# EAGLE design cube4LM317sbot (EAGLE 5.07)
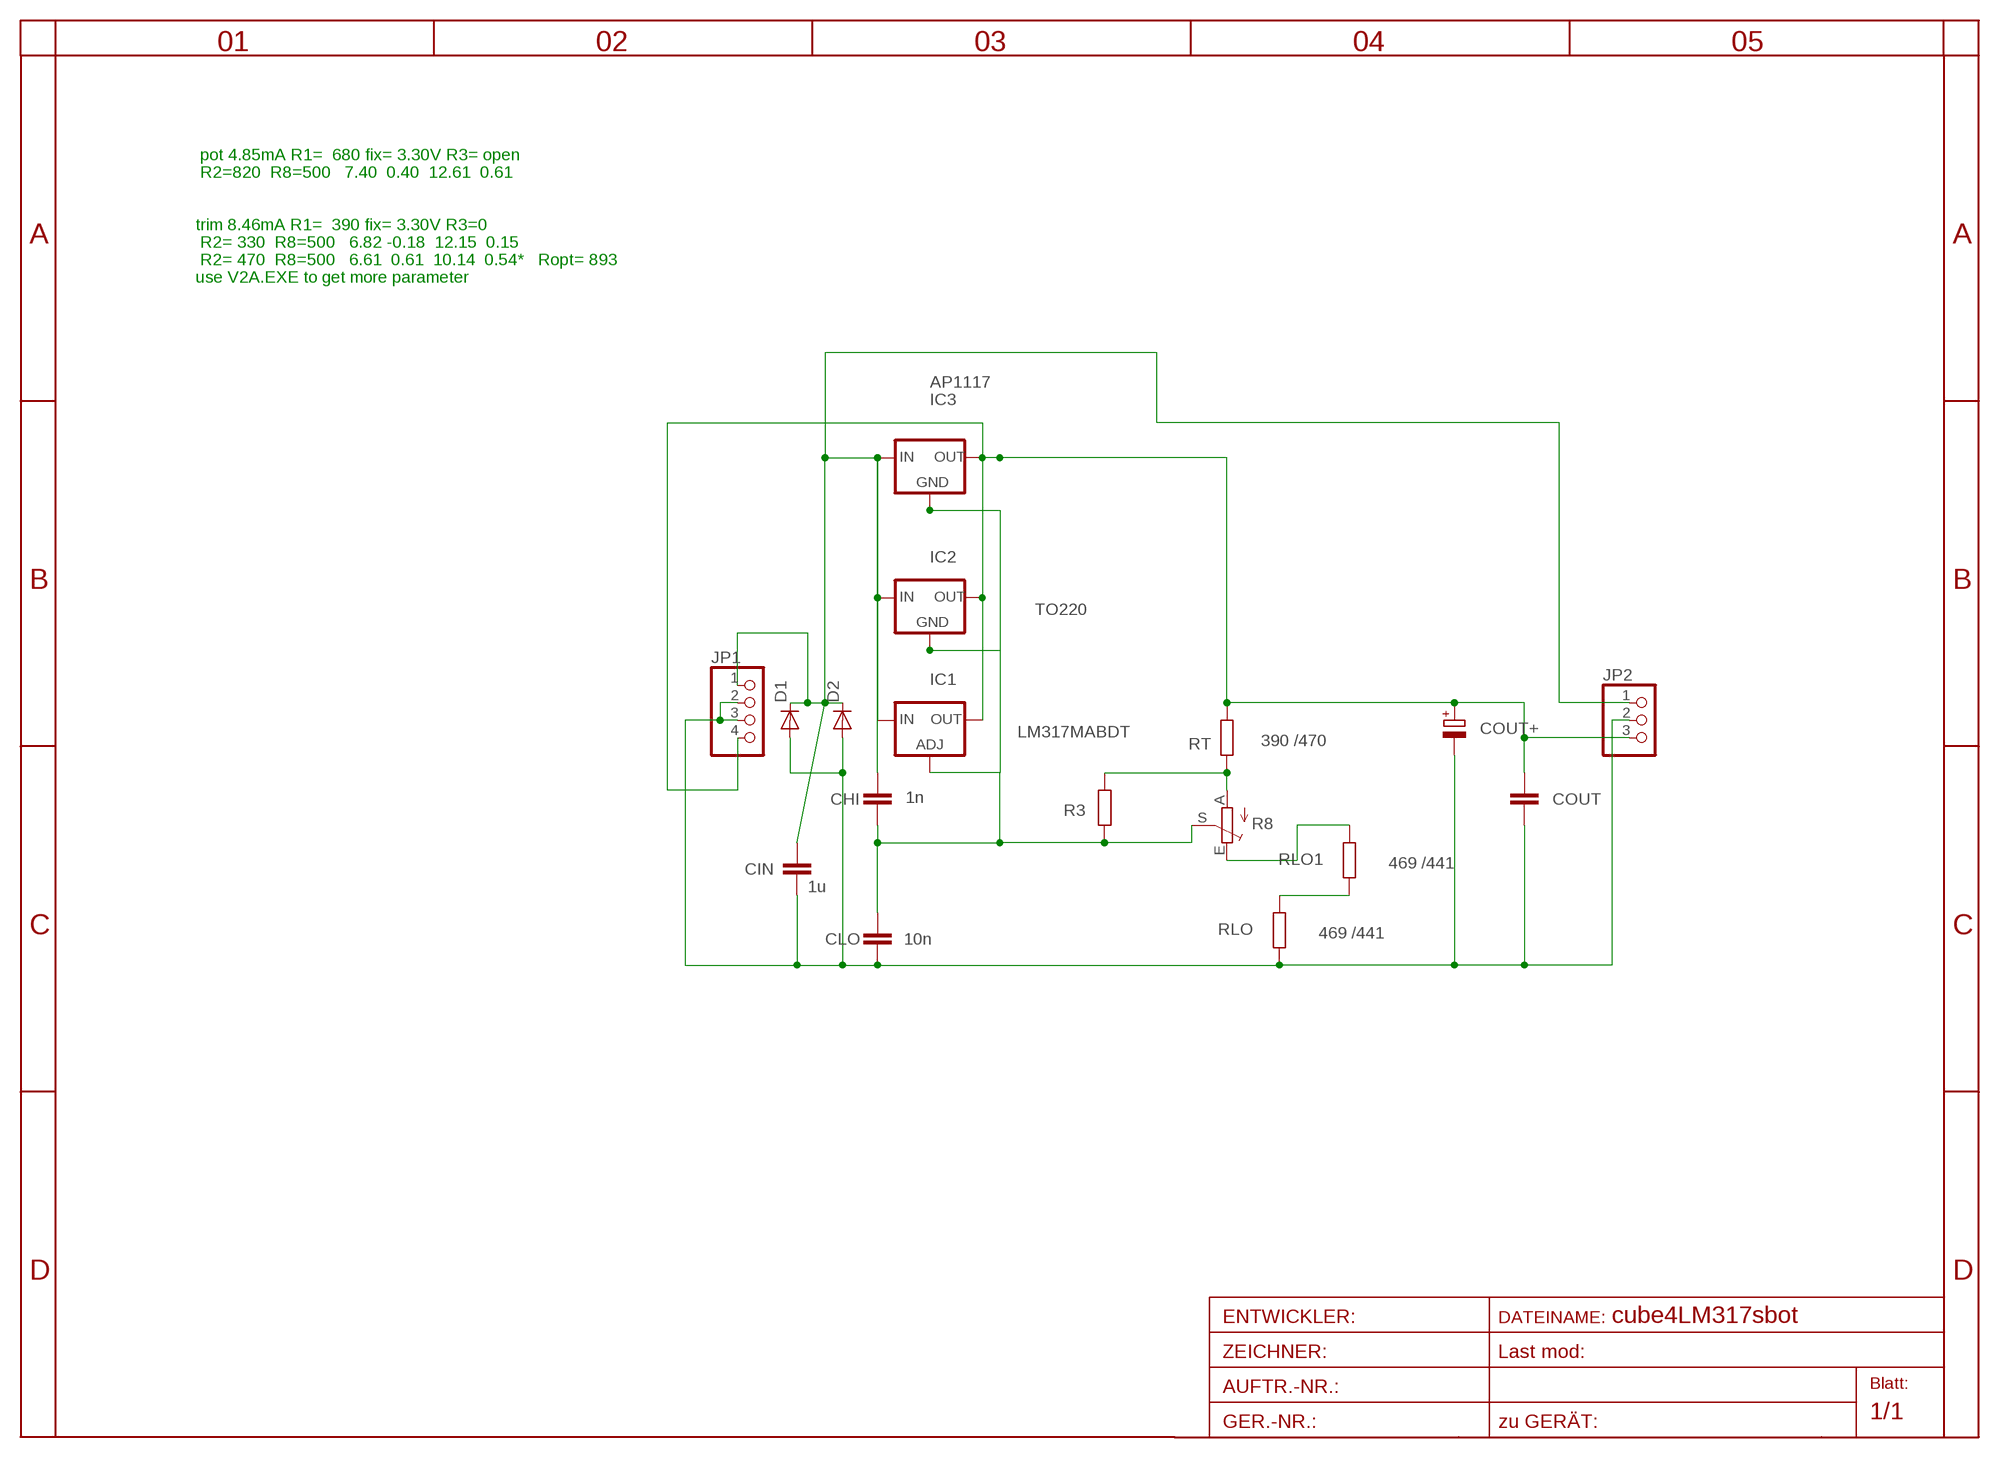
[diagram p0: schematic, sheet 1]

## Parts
CHI  1n  C-EUC0805  [C0805]
CIN  1u  C-EUC1206  [C1206]
CLO  10n  C-EUC0805  [C0805]
COUT  C-EUC1206  [C1206]
COUT+  CPOL-EUE2.5-6  [E2,5-6]
D1  DIODE-MINIMELF  [MINIMELF]
D2  DIODE-MINIMELF  [MINIMELF]
IC1  LM317MABDT  [DPACK]
IC2  TO220  78XXS  [78XXS]
IC3  AP1117  [SOT223]
JP1  PINHD-1X4  [1X04]
JP2  PINHD-1X3  [1X03]
R3  R-EU_R0805  [R0805]
R8  TRIM_EU-RAND160  [RANDL]
RLO  469 /441  R-EU_R0805  [R0805]
RLO1  469 /441  R-EU_R0805  [R0805]
RT  390 /470  R-EU_R0805  [R0805]

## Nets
GND: CIN.2 CLO.2 COUT+.- COUT.2 D1.A D2.A JP1.2 JP1.3 JP2.2 RLO.1
IN: CHI.1 CIN.1 D1.C D2.C IC1.3(IN) IC2.IN IC3.3(IN) JP1.1 JP2.1
N$1: R8.E RLO1.2
N$2: RLO1.1 RLO.2
N$4: CHI.2 CLO.1 IC1.1(ADJ) IC2.GND IC3.1(GND) R3.1 R8.S
N$7: R3.2 R8.A RT.1
OUT: COUT+.+ COUT.1 IC1.4(OUT) IC2.OUT IC3.2(OUT) IC3.4(TAB) JP1.4 JP2.3 RT.2

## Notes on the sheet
- pot 4.85mA R1=  680 fix= 3.30V R3= open
- R2=820  R8=500   7.40  0.40  12.61  0.61
- trim 8.46mA R1=  390 fix= 3.30V R3=0
- R2= 330  R8=500   6.82 -0.18  12.15  0.15
- R2= 470  R8=500   6.61  0.61  10.14  0.54*   Ropt= 893
- use V2A.EXE to get more parameter

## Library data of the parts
CHI CIN CLO COUT = rcl:C-EU: CAPACITOR, European symbol
COUT+ = rcl:CPOL-EU: POLARIZED CAPACITOR, European symbol
D1 D2 = diode-1:DIODE-: DIODE
IC1 = v-reg:LM317?*: 500 mA Adjustable Output Positive Voltage Regulator Source: http://www.onsemi.co.jp .. LM317M-D.PDF
IC2 = v-reg:78XXS: VOLTAGE REGULATOR
IC3 = v-reg:AP1117
JP1 = pinhead:PINHD-1X4: PIN HEADER
JP2 = pinhead:PINHD-1X3: PIN HEADER
R3 RLO RLO1 RT = rcl:R-EU_: RESISTOR, European symbol
R8 = pot:TRIM_EU-: POTENTIOMETER

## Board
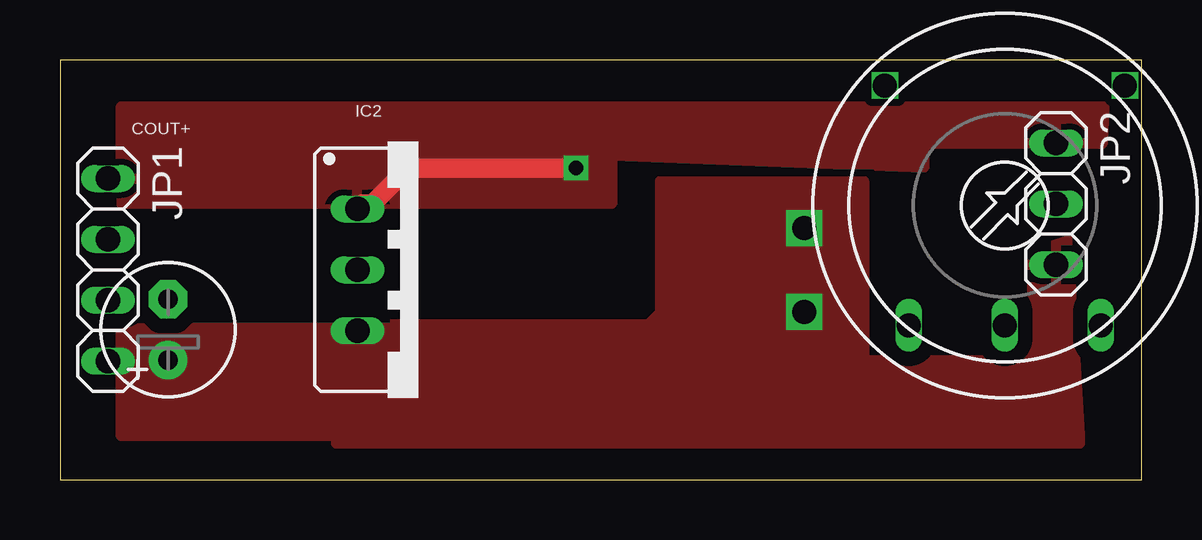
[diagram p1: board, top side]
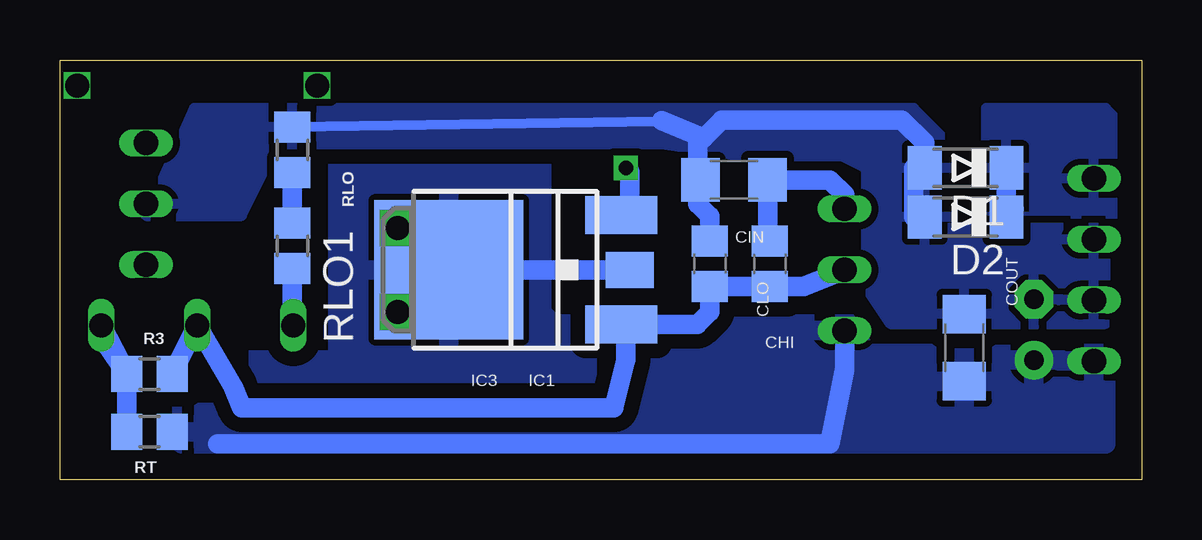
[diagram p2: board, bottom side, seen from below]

Size 45.08 x 17.5 mm. Coordinates in mm from the lower left corner, seen from the top.
Outline: 0,0 45.08,0 45.08,17.5 0,17.5 0,0
Copper layers (1*16): Top 0.035mm / dielectric 1.5mm / Bottom 0.035mm
Design rules "default": minimum track width 10mil, minimum drill 20mil, track to track 8mil, track to pad 8mil, pad to pad 8mil, via to via 8mil, smd to smd 8mil, copper to edge 40mil, drill to drill 8mil, minimum pad ring 1mil, minimum via ring 8mil, stop-mask expansion 4mil, vias tented up to drill 0mil, thermal gap 10mil

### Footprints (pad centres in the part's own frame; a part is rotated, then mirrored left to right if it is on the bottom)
C0805 = smd 1.3 x 1.5: 1 -0.95,0; 2 0.95,0
C1206 = smd 1.6 x 1.8: 1 -1.4,0; 2 1.4,0
E2,5-6 = drill 0.8 pad 1.6 round: + -1.27,0 | drill 0.8 pad 1.6 octagon: - 1.27,0
MINIMELF = smd 1.4 x 1.8: A 1.7,0; C -1.7,0
DPACK = smd 1.6 x 3: 1 -2.28,-4.8; 3 2.28,-4.8 | smd 5.8 x 6.2: 4 0,2.38
78XXS = drill 1.016 long: GND 0,-2.54; IN -2.54,-2.54; OUT 2.54,-2.54
SOT223 = smd 1.5 x 2: 1 -2.3,-3.15; 2 0,-3.15; 3 2.3,-3.15 | smd 3.8 x 2: 4 0,3.15
1X04 = drill 1.016 long: 1 -3.81,0; 2 -1.27,0; 3 1.27,0; 4 3.81,0
1X03 = drill 1.016 long: 1 -2.54,0; 2 0,0; 3 2.54,0
R0805 = smd 1.3 x 1.5: 1 -0.95,0; 2 0.95,0
RANDL = drill 1 long: A -4,5; E 4,5; S 0,5 | drill 1 square: P$1 -5,-5; P$2 5,-5

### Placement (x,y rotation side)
CHI  15.5,9 270 bottom
CIN  17,12.5 180 bottom
CLO  18,9 90 bottom
COUT  7.4,5.5 90 bottom
COUT+  4.5,6.25 90 top
D1  7.35,13 180 bottom
D2  7.35,10.95 180 bottom
IC1  26.5,8.75 90 bottom
IC2  14.93,8.75 270 top
IC3  24.5,8.75 90 bottom
JP1  2,8.75 270 top
JP2  41.5,11.5 270 top
R3  41.35,4.4 180 bottom
R8  39.37,11.43 180 top
RLO  35.4,13.75 270 bottom
RLO1  35.4,9.75 270 bottom
RT  41.35,2 0 bottom

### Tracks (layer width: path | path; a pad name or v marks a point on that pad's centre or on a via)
GND
  Bottom 0.406: RLO.1 20.06,14.92 20.01,14.97
  Bottom 0.813: CLO.2 18,11 18.5,11.5 18.5,12.6 | D2.A 9.5,10.95 9.5,13 D1.A 9.05,14.05 10,15 17.5,15 18.25,14.25 | 18.25,14.25 18.5,14 18.5,12.6 | 18.5,12.6 CIN.2 | 18.25,14.25 20.01,14.97
  pour Bottom (isolate 0.305): 1.5,10.5 8,10.5 8,14 9.5,15.5 39.5,15.5 41.5,11 37.5,11 36.5,13 36.5,14 20,14 17.1,13.55 16,13.5 12.5,13.5 11.5,13 11.5,8 10.5,6.5 1.5,6.5
IN  (via drill 0.6)
  Top 0.813: v21.5,13 14.5,13 13,11.5 12.6,11.5 IC2.IN
  Bottom 0.406: IC1.3 21.35,11.03 IC3.3
  Bottom 0.813: IC2.IN 12.39,11.89 13,12.5 CIN.1 15.6,10.05 CHI.1 | 5.31,11.29 D2.C D1.C | IC3.3 21.35,12.85 v21.5,13
  pour Top (isolate 0.305, rank 2): 2.54,15.56 43.5,15.56 43.5,15.5 43.44,14 36,14 36,13 23,13.5 23,11.5 2.54,11.5
  pour Bottom (isolate 0.305, rank 2): 1,10.5 1,15 1.5,15.5 6.5,15.5 6.5,11.5 5.5,10 1.5,10
N$1
  Bottom 0.813: RLO1.2 35.4,6.46 R8.E
N$2
  Bottom 0.813: RLO1.1 RLO.2
N$4
  Bottom 0.406: IC1.1 21.35,6.47 IC3.1
  Bottom 0.813: IC2.GND 14.09,8.05 CHI.2 CLO.1 18,7 18.53,6.47 IC1.1 | R3.1 39.4,6.4 R8.S 37.87,3.87 37.5,3 22,3 21.5,5 21.5,6.3 IC3.1
N$7
  Bottom 0.813: R3.2 43.34,6.4 R8.A | R3.2 43.2,5.72 | RT.1 R3.2
OUT  (via drill 1)
  Bottom 0.406: IC1.4 31,8.75 v31,7
  Bottom 0.813: IC2.OUT 12.39,4.61 13,1.5 38.5,1.5 | IC1.4 28.5,8.37 28.03,8.37 IC3.4 IC3.2
  other vias: 31,10.5
  pour Top (isolate 0.61, no thermals): 2.54,6.35 20.01,6.35 20.01,1.81 2.54,1.81
  pour Bottom (isolate 0.61, rank 2): 25,14 33.5,14 33.5,5 40,5 40,1.5 1.5,1.5 1.5,6.5 24.5,6.5 25,7
  pour Top (isolate 0.61): 25,12.45 33.5,12.45 33.5,5 40.5,5 40.5,9.5 42,10 42.5,1.5 11.5,1.5 11.5,6.5 24.5,6.5 25,7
